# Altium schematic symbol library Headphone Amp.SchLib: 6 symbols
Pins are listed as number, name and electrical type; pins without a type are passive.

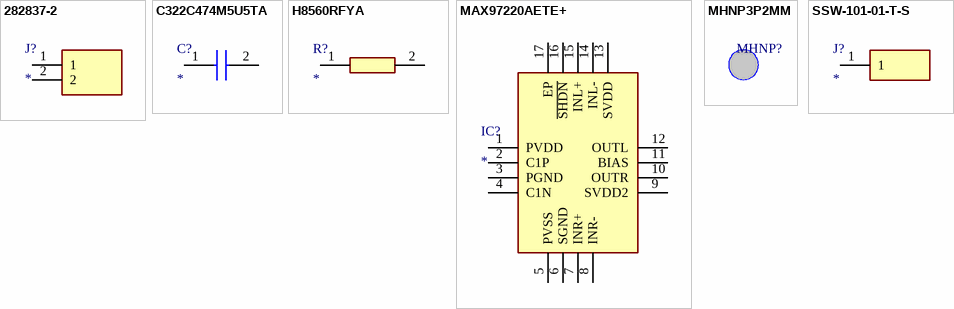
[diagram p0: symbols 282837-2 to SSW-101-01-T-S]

## 282837-2
designator J?
Connector; Manufacturer_Name: TE Connectivity; Manufacturer_Part_Number: 282837-2
footprint 2828372
pins: 1, 2

## C322C474M5U5TA
designator C?
Capacitor; Manufacturer_Name: KEMET; Manufacturer_Part_Number: C322C474M5U5TA; Description: GoldMax 300 Comm Z5U
footprint C322C474M5U5TA
pins: 1, 2

## H8560RFYA
designator R?
Resistor; Manufacturer_Name: TE Connectivity; Manufacturer_Part_Number: H8560RFYA; Description: Metal Film Resistors - Through Hole H8 560R 1% 15PPM
footprint RESAD1800W60L720D270
pins: 1, 2

## MAX97220AETE+
designator IC?
Integrated Circuit; Manufacturer_Name: Analog Devices; Manufacturer_Part_Number: MAX97220AETE+; Description: IC AMP CLSS AB STER 125MW 16TQFN
footprint QFN50P300X300X80-17N
pins: 1 PVDD, 2 C1P, 3 PGND, 4 C1N, 5 PVSS, 6 SGND, 7 INR+, 8 INR-, 9 SVDD2, 10 OUTR, 11 BIAS, 12 OUTL, 13 SVDD, 14 INL-, 15 INL+, 16 ~{SHDN}, 17 EP

## MHNP3P2MM
designator MHNP?, comment Mounting Hole Non-Plated 3.2mm  (value not drawn)
Mounting Hole Non-Plated 3.2mm drill hole
footprint MTHNP3P2MM (Mounting Hole Non-Plated 3.2mm)

## SSW-101-01-T-S
designator J?
Connector; Manufacturer_Name: SAMTEC; Manufacturer_Part_Number: SSW-101-01-T-S; Description: 1 Position
footprint SSW-101-XX-YYY-S
pins: 1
